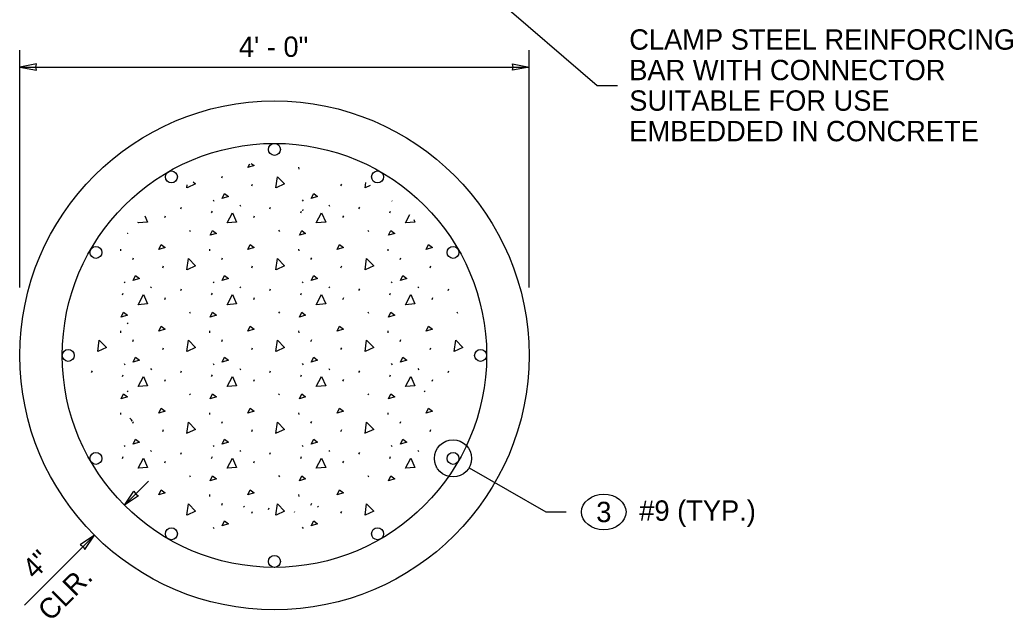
# Model space of a CAD drawing. Extents: x 99862 to 104211, y 98939 to 105076.
# Drawn here: x 101523 to 102303, y 100649 to 101119 of the extents above; entities that cross this region are included whole.
import ezdxf

# ---------------------------------------------------------------- set-up
doc = ezdxf.new("R2010")
doc.units = 0
for name, color, linetype in [('Level 10', 7, 'Continuous'), ('Level 12', 7, 'Continuous'), ('Level 15', 7, 'Continuous'), ('Level 2', 7, 'Continuous'), ('Level 20', 7, 'Continuous')]:
    doc.layers.add(name, color=color, linetype=linetype)

msp = doc.modelspace()

# ---------------------------------------------------------------- linework, layer by layer
at = {"layer": 'Level 10'}
for p, q in [((101745.32, 100968.83), (101745.84, 100970)), ((101607.49, 100880.94), (101608.01, 100880.16)), ((101607.49, 100827.34), (101608.01, 100826.57)), ((101840.82, 100827.34), (101841.34, 100826.57)), ((101698.75, 100736.65), (101699.27, 100735.88)), ((101718.46, 100734.12), (101718.98, 100735.29)), ((101757.09, 100736.65), (101757.56, 100735.94)), ((101738.94, 100732.03), (101739.18, 100732.58))]:
    msp.add_line(p, q, dxfattribs=at)
msp.add_lwpolyline([(101609.57, 100805.93), (101611.43, 100804.01), (101610.58, 100803.61)], dxfattribs=at)
for centre, radius in [((101723.16, 100855.25), 166.67), ((101723.16, 101017.22), 4.7), ((101642.17, 100995.52), 4.7), ((101804.14, 100995.52), 4.7), ((101582.89, 100936.23), 4.7), ((101863.42, 100936.23), 4.7), ((101561.19, 100855.25), 4.7), ((101885.12, 100855.25), 4.7), ((101582.89, 100774.27), 4.7), ((101863.42, 100774.27), 4.7), ((101642.17, 100714.98), 4.7), ((101804.14, 100714.98), 4.7), ((101723.16, 100693.28), 4.7)]:
    msp.add_circle(centre, radius, dxfattribs=at)
at = {"layer": 'Level 12'}
for p, q in [((101742.09, 101003.09), (101742.25, 101001.69)), ((101681.78, 100994.84), (101682.4, 100996.24)), ((101705.4, 100988.47), (101706.03, 100989.87)), ((101775.4, 100988.47), (101776.03, 100989.87)), ((101674.97, 100977.44), (101675.59, 100976.51)), ((101744.97, 100977.44), (101745.59, 100976.51)), ((101815.45, 100976.72), (101815.59, 100976.51)), ((101649.54, 100970.45), (101650.17, 100971.85)), ((101673.79, 100967.2), (101674.41, 100968.6)), ((101695.9, 100973.49), (101696.52, 100972.56)), ((101719.54, 100970.45), (101720.17, 100971.85)), ((101743.79, 100967.2), (101744.41, 100968.6)), ((101765.9, 100973.49), (101766.52, 100972.56)), ((101789.54, 100970.45), (101790.17, 100971.85)), ((101813.79, 100967.2), (101814.41, 100968.6)), ((101636.96, 100963.63), (101637.58, 100965.03)), ((101706.96, 100963.63), (101707.58, 100965.03)), ((101776.96, 100963.63), (101777.58, 100965.03)), ((101656.38, 100953.68), (101657, 100952.75)), ((101726.38, 100953.68), (101727, 100952.75)), ((101796.38, 100953.68), (101797, 100952.75)), ((101602.09, 100938.78), (101602.25, 100937.38)), ((101672.09, 100938.78), (101672.25, 100937.38)), ((101742.09, 100938.78), (101742.25, 100937.38)), ((101812.09, 100938.78), (101812.25, 100937.38)), ((101611.78, 100930.53), (101612.4, 100931.93)), ((101681.78, 100930.53), (101682.4, 100931.93)), ((101751.78, 100930.53), (101752.4, 100931.93)), ((101821.78, 100930.53), (101822.4, 100931.93)), ((101635.4, 100924.16), (101636.03, 100925.56)), ((101705.4, 100924.16), (101706.03, 100925.56)), ((101775.4, 100924.16), (101776.03, 100925.56)), ((101845.4, 100924.16), (101846.03, 100925.56)), ((101604.97, 100913.13), (101605.59, 100912.2)), ((101625.9, 100909.17), (101626.52, 100908.24)), ((101649.54, 100906.13), (101650.17, 100907.53)), ((101674.97, 100913.13), (101675.59, 100912.2)), ((101695.9, 100909.17), (101696.52, 100908.24)), ((101719.54, 100906.13), (101720.17, 100907.53)), ((101744.97, 100913.13), (101745.59, 100912.2)), ((101765.9, 100909.17), (101766.52, 100908.24)), ((101789.54, 100906.13), (101790.17, 100907.53)), ((101814.97, 100913.13), (101815.59, 100912.2)), ((101835.9, 100909.17), (101836.52, 100908.24)), ((101859.54, 100906.13), (101860.17, 100907.53)), ((101603.79, 100902.89), (101604.41, 100904.29)), ((101636.96, 100899.31), (101637.58, 100900.71)), ((101673.79, 100902.89), (101674.41, 100904.29)), ((101706.96, 100899.31), (101707.58, 100900.71)), ((101743.79, 100902.89), (101744.41, 100904.29)), ((101776.96, 100899.31), (101777.58, 100900.71)), ((101813.79, 100902.89), (101814.41, 100904.29)), ((101846.96, 100899.31), (101847.58, 100900.71)), ((101656.38, 100889.37), (101657, 100888.44)), ((101726.38, 100889.37), (101727, 100888.44)), ((101796.38, 100889.37), (101797, 100888.44)), ((101866.38, 100889.37), (101867, 100888.44)), ((101602.09, 100874.46), (101602.25, 100873.06)), ((101611.78, 100866.21), (101612.4, 100867.61)), ((101672.09, 100874.46), (101672.25, 100873.06)), ((101681.78, 100866.21), (101682.4, 100867.61)), ((101742.09, 100874.46), (101742.25, 100873.06)), ((101751.78, 100866.21), (101752.4, 100867.61)), ((101812.09, 100874.46), (101812.25, 100873.06)), ((101821.78, 100866.21), (101822.4, 100867.61)), ((101635.4, 100859.84), (101636.03, 100861.24)), ((101705.4, 100859.84), (101706.03, 100861.24)), ((101775.4, 100859.84), (101776.03, 100861.24)), ((101845.4, 100859.84), (101846.03, 100861.24)), ((101604.97, 100848.81), (101605.59, 100847.88)), ((101625.9, 100844.86), (101626.52, 100843.93)), ((101674.97, 100848.81), (101675.59, 100847.88)), ((101695.9, 100844.86), (101696.52, 100843.93)), ((101744.97, 100848.81), (101745.59, 100847.88)), ((101765.9, 100844.86), (101766.52, 100843.93)), ((101814.97, 100848.81), (101815.59, 100847.88)), ((101835.9, 100844.86), (101836.52, 100843.93)), ((101579.54, 100841.82), (101580.17, 100843.22)), ((101603.79, 100838.57), (101604.41, 100839.97)), ((101636.96, 100835), (101637.58, 100836.4)), ((101649.54, 100841.82), (101650.17, 100843.22)), ((101673.79, 100838.57), (101674.41, 100839.97)), ((101706.96, 100835), (101707.58, 100836.4)), ((101719.54, 100841.82), (101720.17, 100843.22)), ((101743.79, 100838.57), (101744.41, 100839.97)), ((101776.96, 100835), (101777.58, 100836.4)), ((101789.54, 100841.82), (101790.17, 100843.22)), ((101813.79, 100838.57), (101814.41, 100839.97)), ((101846.96, 100835), (101847.58, 100836.4)), ((101859.54, 100841.82), (101860.17, 100843.22)), ((101656.38, 100825.05), (101657, 100824.12)), ((101726.38, 100825.05), (101727, 100824.12)), ((101796.38, 100825.05), (101797, 100824.12)), ((101602.09, 100810.15), (101602.25, 100808.75)), ((101672.09, 100810.15), (101672.25, 100808.75)), ((101742.09, 100810.15), (101742.25, 100808.75)), ((101812.09, 100810.15), (101812.25, 100808.75)), ((101611.78, 100801.9), (101612.4, 100803.3)), ((101635.4, 100795.53), (101636.03, 100796.93)), ((101681.78, 100801.9), (101682.4, 100803.3)), ((101705.4, 100795.53), (101706.03, 100796.93)), ((101751.78, 100801.9), (101752.4, 100803.3)), ((101775.4, 100795.53), (101776.03, 100796.93)), ((101821.78, 100801.9), (101822.4, 100803.3)), ((101845.4, 100795.53), (101846.03, 100796.93)), ((101604.97, 100784.5), (101605.59, 100783.57)), ((101674.97, 100784.5), (101675.59, 100783.57)), ((101744.97, 100784.5), (101745.59, 100783.57)), ((101814.97, 100784.5), (101815.59, 100783.57)), ((101603.79, 100774.26), (101604.41, 100775.66)), ((101625.9, 100780.54), (101626.52, 100779.61)), ((101649.54, 100777.5), (101650.17, 100778.9)), ((101673.79, 100774.26), (101674.41, 100775.66)), ((101695.9, 100780.54), (101696.52, 100779.61)), ((101719.54, 100777.5), (101720.17, 100778.9)), ((101743.79, 100774.26), (101744.41, 100775.66)), ((101765.9, 100780.54), (101766.52, 100779.61)), ((101789.54, 100777.5), (101790.17, 100778.9)), ((101813.79, 100774.26), (101814.41, 100775.66)), ((101835.9, 100780.54), (101836.52, 100779.61)), ((101636.96, 100770.68), (101637.58, 100772.08)), ((101706.96, 100770.68), (101707.58, 100772.08)), ((101776.96, 100770.68), (101777.58, 100772.08)), ((101850.07, 100768.48), (101850.22, 100767.08)), ((101656.38, 100760.74), (101657, 100759.81)), ((101726.38, 100760.74), (101727, 100759.81)), ((101796.38, 100760.74), (101797, 100759.81)), ((101672.09, 100745.83), (101672.25, 100744.43)), ((101742.09, 100745.83), (101742.25, 100744.43)), ((101681.78, 100737.58), (101682.4, 100738.98)), ((101751.78, 100737.58), (101752.4, 100738.98)), ((101705.4, 100731.21), (101706.03, 100732.61)), ((101775.4, 100731.21), (101776.03, 100732.61)), ((101674.97, 100720.18), (101675.59, 100719.25)), ((101744.97, 100720.18), (101745.59, 100719.25))]:
    msp.add_line(p, q, dxfattribs=at)
for points in [[(101704.99, 101006.14), (101707.3, 101004.4), (101702.33, 101002.85)], [(101702.33, 101002.85), (101703.79, 101005.89)], [(101659.36, 100991.81), (101661.11, 100990), (101654.46, 100986.92)], [(101724.31, 100986.87), (101725.54, 100995.75), (101731.11, 100990), (101724.46, 100986.92)], [(101654.31, 100986.87), (101654.65, 100989.36)], [(101794.31, 100986.87), (101794.91, 100991.19)], [(101798.39, 100988.74), (101794.46, 100986.92)], [(101682.09, 100978.53), (101683.96, 100982.41), (101687.07, 100980.08), (101682.09, 100978.53)], [(101752.09, 100978.53), (101753.96, 100982.41), (101757.07, 100980.08), (101752.09, 100978.53)], [(101621.3, 100964.84), (101623.44, 100960.06), (101616.13, 100959.44)], [(101685.98, 100959.44), (101690.17, 100967.36), (101693.44, 100960.06), (101686.13, 100959.44)], [(101755.98, 100959.44), (101760.17, 100967.36), (101763.44, 100960.06), (101756.13, 100959.44)], [(101825.98, 100959.44), (101829.4, 100965.89)], [(101832.57, 100961.99), (101833.44, 100960.06), (101826.13, 100959.44)], [(101615.98, 100959.44), (101616.41, 100960.25)], [(101672.7, 100949.64), (101674.56, 100953.53), (101677.67, 100951.2), (101672.7, 100949.64)], [(101742.7, 100949.64), (101744.56, 100953.53), (101747.67, 100951.2), (101742.7, 100949.64)], [(101812.7, 100949.64), (101814.56, 100953.53), (101817.67, 100951.2), (101812.7, 100949.64)], [(101607.59, 100951.26), (101607.67, 100951.2), (101607.52, 100951.15)], [(101632.33, 100938.53), (101634.19, 100942.42), (101637.3, 100940.09), (101632.33, 100938.53)], [(101702.33, 100938.53), (101704.19, 100942.42), (101707.3, 100940.09), (101702.33, 100938.53)], [(101772.33, 100938.53), (101774.19, 100942.42), (101777.3, 100940.09), (101772.33, 100938.53)], [(101842.33, 100938.53), (101844.19, 100942.42), (101847.3, 100940.09), (101842.33, 100938.53)], [(101654.31, 100922.55), (101655.54, 100931.43), (101661.11, 100925.68), (101654.46, 100922.6)], [(101724.31, 100922.55), (101725.54, 100931.43), (101731.11, 100925.68), (101724.46, 100922.6)], [(101794.31, 100922.55), (101795.54, 100931.43), (101801.11, 100925.68), (101794.46, 100922.6)], [(101612.09, 100914.21), (101613.96, 100918.1), (101617.07, 100915.77), (101612.09, 100914.21)], [(101682.09, 100914.21), (101683.96, 100918.1), (101687.07, 100915.77), (101682.09, 100914.21)], [(101752.09, 100914.21), (101753.96, 100918.1), (101757.07, 100915.77), (101752.09, 100914.21)], [(101822.09, 100914.21), (101823.96, 100918.1), (101827.07, 100915.77), (101822.09, 100914.21)], [(101615.98, 100895.12), (101620.17, 100903.04), (101623.44, 100895.74), (101616.13, 100895.12)], [(101685.98, 100895.12), (101690.17, 100903.04), (101693.44, 100895.74), (101686.13, 100895.12)], [(101755.98, 100895.12), (101760.17, 100903.04), (101763.44, 100895.74), (101756.13, 100895.12)], [(101825.98, 100895.12), (101830.17, 100903.04), (101833.44, 100895.74), (101826.13, 100895.12)], [(101602.7, 100885.33), (101604.56, 100889.21), (101607.67, 100886.88), (101602.7, 100885.33)], [(101672.7, 100885.33), (101674.56, 100889.21), (101677.67, 100886.88), (101672.7, 100885.33)], [(101742.7, 100885.33), (101744.56, 100889.21), (101747.67, 100886.88), (101742.7, 100885.33)], [(101812.7, 100885.33), (101814.56, 100889.21), (101817.67, 100886.88), (101812.7, 100885.33)], [(101632.33, 100874.22), (101634.19, 100878.1), (101637.3, 100875.77), (101632.33, 100874.22)], [(101702.33, 100874.22), (101704.19, 100878.1), (101707.3, 100875.77), (101702.33, 100874.22)], [(101772.33, 100874.22), (101774.19, 100878.1), (101777.3, 100875.77), (101772.33, 100874.22)], [(101842.33, 100874.22), (101844.19, 100878.1), (101847.3, 100875.77), (101842.33, 100874.22)], [(101584.31, 100858.24), (101585.54, 100867.12), (101591.11, 100861.37), (101584.46, 100858.29)], [(101654.31, 100858.24), (101655.54, 100867.12), (101661.11, 100861.37), (101654.46, 100858.29)], [(101724.31, 100858.24), (101725.54, 100867.12), (101731.11, 100861.37), (101724.46, 100858.29)], [(101794.31, 100858.24), (101795.54, 100867.12), (101801.11, 100861.37), (101794.46, 100858.29)], [(101864.31, 100858.24), (101865.54, 100867.12), (101871.11, 100861.37), (101864.46, 100858.29)], [(101612.09, 100849.9), (101613.96, 100853.78), (101617.07, 100851.45), (101612.09, 100849.9)], [(101682.09, 100849.9), (101683.96, 100853.78), (101687.07, 100851.45), (101682.09, 100849.9)], [(101752.09, 100849.9), (101753.96, 100853.78), (101757.07, 100851.45), (101752.09, 100849.9)], [(101822.09, 100849.9), (101823.96, 100853.78), (101827.07, 100851.45), (101822.09, 100849.9)], [(101615.98, 100830.81), (101620.17, 100838.73), (101623.44, 100831.43), (101616.13, 100830.81)], [(101685.98, 100830.81), (101690.17, 100838.73), (101693.44, 100831.43), (101686.13, 100830.81)], [(101755.98, 100830.81), (101760.17, 100838.73), (101763.44, 100831.43), (101756.13, 100830.81)], [(101825.98, 100830.81), (101830.17, 100838.73), (101833.44, 100831.43), (101826.13, 100830.81)], [(101602.7, 100821.01), (101604.56, 100824.9), (101607.67, 100822.57), (101602.7, 100821.01)], [(101672.7, 100821.01), (101674.56, 100824.9), (101677.67, 100822.57), (101672.7, 100821.01)], [(101742.7, 100821.01), (101744.56, 100824.9), (101747.67, 100822.57), (101742.7, 100821.01)], [(101812.7, 100821.01), (101814.56, 100824.9), (101817.67, 100822.57), (101812.7, 100821.01)], [(101632.33, 100809.9), (101634.19, 100813.79), (101637.3, 100811.46), (101632.33, 100809.9)], [(101702.33, 100809.9), (101704.19, 100813.79), (101707.3, 100811.46), (101702.33, 100809.9)], [(101772.33, 100809.9), (101774.19, 100813.79), (101777.3, 100811.46), (101772.33, 100809.9)], [(101842.33, 100809.9), (101844.19, 100813.79), (101847.3, 100811.46), (101842.33, 100809.9)], [(101654.31, 100793.92), (101655.54, 100802.8), (101661.11, 100797.05), (101654.46, 100793.97)], [(101724.31, 100793.92), (101725.54, 100802.8), (101731.11, 100797.05), (101724.46, 100793.97)], [(101794.31, 100793.92), (101795.54, 100802.8), (101801.11, 100797.05), (101794.46, 100793.97)], [(101612.09, 100785.58), (101613.96, 100789.47), (101617.07, 100787.14), (101612.09, 100785.58)], [(101682.09, 100785.58), (101683.96, 100789.47), (101687.07, 100787.14), (101682.09, 100785.58)], [(101752.09, 100785.58), (101753.96, 100789.47), (101757.07, 100787.14), (101752.09, 100785.58)], [(101822.09, 100785.58), (101823.96, 100789.47), (101827.07, 100787.14), (101822.09, 100785.58)], [(101615.98, 100766.49), (101620.17, 100774.41), (101623.44, 100767.11), (101616.13, 100766.49)], [(101685.98, 100766.49), (101690.17, 100774.41), (101693.44, 100767.11), (101686.13, 100766.49)], [(101755.98, 100766.49), (101760.17, 100774.41), (101763.44, 100767.11), (101756.13, 100766.49)], [(101825.98, 100766.49), (101830.17, 100774.41), (101833.44, 100767.11), (101826.13, 100766.49)], [(101672.7, 100756.7), (101674.56, 100760.58), (101677.67, 100758.25), (101672.7, 100756.7)], [(101742.7, 100756.7), (101744.56, 100760.58), (101747.67, 100758.25), (101742.7, 100756.7)], [(101812.7, 100756.7), (101814.56, 100760.58), (101817.67, 100758.25), (101812.7, 100756.7)], [(101632.33, 100745.59), (101634.19, 100749.47), (101637.3, 100747.14), (101632.33, 100745.59)], [(101702.33, 100745.59), (101704.19, 100749.47), (101707.3, 100747.14), (101702.33, 100745.59)], [(101772.33, 100745.59), (101774.19, 100749.47), (101777.3, 100747.14), (101772.33, 100745.59)], [(101654.31, 100729.61), (101655.54, 100738.49), (101661.11, 100732.74), (101654.46, 100729.66)], [(101724.31, 100729.61), (101725.54, 100738.49), (101731.11, 100732.74), (101724.46, 100729.66)], [(101794.31, 100729.61), (101795.54, 100738.49), (101801.11, 100732.74), (101794.46, 100729.66)], [(101682.09, 100721.27), (101683.96, 100725.15), (101687.07, 100722.82), (101682.09, 100721.27)], [(101752.09, 100721.27), (101753.96, 100725.15), (101757.07, 100722.82), (101752.09, 100721.27)]]:
    msp.add_lwpolyline(points, dxfattribs=at)
at = {"layer": 'Level 15'}
for p, q in [((101734, 101276.67), (101976.76, 101067.34)), ((101523.16, 100908.58), (101523.16, 101095.25)), ((101923.16, 100908.58), (101923.16, 101095.25)), ((101523.16, 101081.92), (101923.16, 101081.92)), ((101976.76, 101067.34), (101992.76, 101067.34)), ((101876.05, 100766.97), (101936.37, 100732.15)), ((101624.16, 100756.25), (101605.31, 100737.4)), ((101936.37, 100732.15), (101952.37, 100732.15)), ((101581.74, 100713.83), (101526.89, 100658.98))]:
    msp.add_line(p, q, dxfattribs=at)
for points in [[(101523.16, 101081.92), (101536.26, 101079.35), (101535.65, 101081.92), (101536.26, 101084.49)], [(101923.16, 101081.92), (101910.05, 101079.35), (101910.66, 101081.92), (101910.05, 101084.49)], [(101605.31, 100737.4), (101612.75, 100748.48), (101614.14, 100746.23), (101616.39, 100744.85)], [(101581.74, 100713.83), (101570.65, 100706.38), (101572.9, 100704.99), (101574.29, 100702.74)]]:
    msp.add_lwpolyline(points, close=True, dxfattribs=at)
msp.add_circle((101863.42, 100774.27), 14.58, dxfattribs=at)
at = {"layer": 'Level 2'}
msp.add_circle((101723.16, 100855.25), 200, dxfattribs=at)
at = {"layer": 'Level 20'}
msp.add_ellipse((101981.87, 100732.15), major_axis=(-17.5, 0), ratio=0.8, dxfattribs=at)

# ---------------------------------------------------------------- texts
for s, rotation, p in [('CLAMP STEEL REINFORCING', 360, (102001.88, 101095.59)), ('BAR WITH CONNECTOR', 360, (102001.88, 101071.59)), ('SUITABLE FOR USE ', 360, (102001.88, 101047.59)), ('EMBEDDED IN CONCRETE', 360, (102001.88, 101023.59)), ('4" ', 45, (101534.93, 100678.55)), ('CLR.', 45, (101547.07, 100645.44))]:
    msp.add_text(s, height=16, rotation=rotation, dxfattribs=at).set_placement(p)
for s, p in [('4\' - 0"', (101695.22, 101089.92)), ('#9 (TYP.)', (102009.75, 100725.24)), ('3', (101975.96, 100724.15))]:
    msp.add_text(s, height=16, dxfattribs=at).set_placement(p)

doc.saveas('drawing.dxf')
